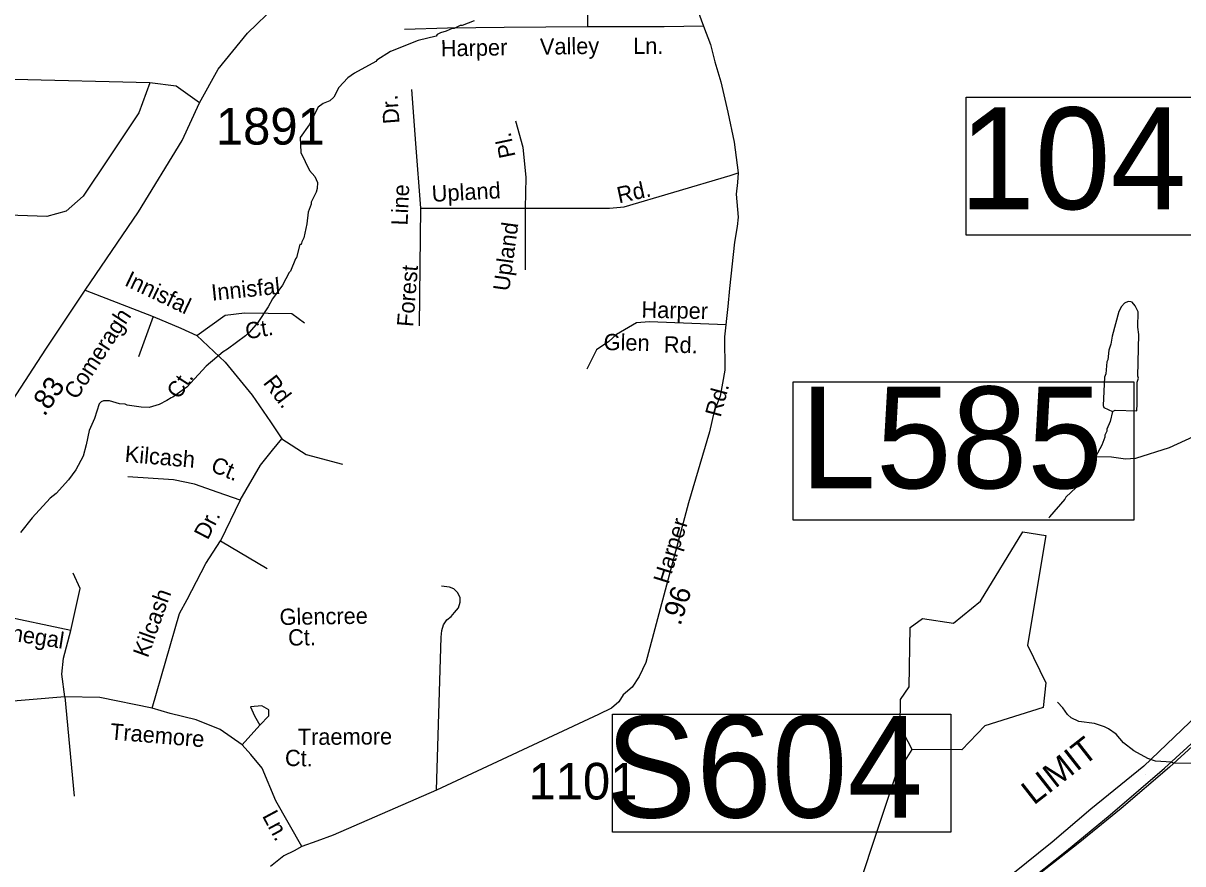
# Model space of a CAD drawing. Extents: x 1551653 to 1702041, y 811336 to 920032.
# Drawn here: x 1584838 to 1589513, y 832897 to 836287 of the extents above; entities that cross this region are included whole.
import ezdxf

# ---------------------------------------------------------------- set-up
doc = ezdxf.new("R2010")
doc.units = 0
for name, color, linetype in [('Old_Level_10', 7, 'Continuous'), ('Old_Level_11', 7, 'Continuous'), ('Old_Level_17', 7, 'Continuous'), ('Old_Level_19', 7, 'Continuous'), ('Old_Level_27', 7, 'Continuous'), ('Old_Level_3', 7, 'Continuous'), ('Old_Level_31', 7, 'Continuous'), ('Old_Level_32', 7, 'Continuous'), ('Old_Level_35', 7, 'Continuous'), ('Old_Level_59', 7, 'Continuous'), ('Old_Level_60', 7, 'Continuous'), ('Old_Level_62', 7, 'Continuous'), ('Old_Level_8', 7, 'Continuous')]:
    doc.layers.add(name, color=color, linetype=linetype)

msp = doc.modelspace()

# ---------------------------------------------------------------- linework, layer by layer
at = {"layer": 'Old_Level_27'}
for points in [[(1585234.947, 830561.484), (1585517.339, 830735.004), (1585731.831, 830866.826), (1586987.103, 831603.033), (1587589.659, 831954.633), (1587938.231, 832161.107), (1588134.784, 832284.159), (1588329.681, 832416.103), (1588524.132, 832555.629), (1588689.213, 832669.856), (1588867.775, 832809.715), (1589044.529, 832949.711), (1589220.001, 833094.479), (1589439.862, 833283.072), (1589622.448, 833449.201), (1589847.716, 833655.674), (1590031.346, 833822.704)], [(1589848.535, 833751.256), (1589658.595, 833580.462), (1589540.265, 833466.424), (1589356.341, 833290.294), (1589142.929, 833117.047), (1588986.427, 832984.144), (1588827.554, 832855.988), (1588637.855, 832715.965), (1588488.13, 832602.006), (1588294.582, 832463.126), (1588074.597, 832322.953), (1587900.805, 832204.617), (1587556.975, 832002.89), (1586266.762, 831248.172), (1585718.938, 830927.99), (1585491.044, 830800.795), (1585324.103, 830701.782)]]:
    msp.add_lwpolyline(points, dxfattribs=at)
at = {"layer": 'Old_Level_3'}
msp.add_lwpolyline([(1589942.504, 833729.014), (1589853.101, 833648.633), (1589643.948, 833455.064), (1589459.401, 833286.101), (1589265.012, 833120.419), (1589091.128, 832979.343), (1588910.682, 832837.447), (1588732.697, 832698.012), (1588562.913, 832578.262), (1588369.344, 832439.646), (1588158.551, 832306.773), (1587952.678, 832177.18), (1587662.325, 832005.756), (1587272.726, 831767.075), (1585533.064, 830743.455)], dxfattribs=at)
at = {"layer": 'Old_Level_31'}
msp.add_line((1589362.127, 833257.432), (1589362.127, 833257.432), dxfattribs=at)
for points in [[(1588639.098, 835987.967), (1589616.623, 835987.967), (1589616.623, 835431.4), (1588639.098, 835431.4), (1588639.098, 835987.967)], [(1587942.488, 834841.019), (1589315.965, 834841.019), (1589315.965, 834282.562), (1587942.488, 834282.562), (1587942.488, 834841.019)], [(1587213.886, 833499.738), (1588577.986, 833499.738), (1588577.986, 833024.31), (1587213.886, 833024.31), (1587213.886, 833499.738)]]:
    msp.add_lwpolyline(points, dxfattribs=at)
at = {"layer": 'Old_Level_32'}
for points in [[(1584743.185, 834688.866), (1584928.668, 834972.489), (1585088.102, 835210.396), (1585302.519, 835525.68), (1585479.347, 835812.909), (1585548.554, 835965.343), (1585623.924, 836101.704), (1585742.776, 836246.77), (1585855.829, 836357.019), (1585976.808, 836466.891), (1586075.368, 836530.72), (1586150.736, 836559.733), (1586208.732, 836579.846)], [(1587556.5, 836340.045), (1587580.081, 836274.826), (1587609.498, 836200.741), (1587626.5, 836130.541), (1587650.183, 836050.307), (1587679.408, 835927.474), (1587703.808, 835807.074), (1587721.011, 835683.574), (1587718.219, 835644.44), (1587712.042, 835597.612), (1587720.048, 835505.004), (1587716.543, 835466.415), (1587706.028, 835403.269), (1587684.997, 835217.339), (1587678.966, 835144.801), (1587665.807, 835021.604), (1587666.066, 834888.027), (1587648.468, 834782.329), (1587623.941, 834722.062), (1587604.84, 834638.46), (1587520.256, 834352.702), (1587348.427, 833708.432), (1587321.426, 833652.733), (1587292.925, 833609.134), (1587257.373, 833578.629), (1587239.926, 833549.934), (1587209.625, 833524.334), (1587157.226, 833499.134), (1586504.528, 833194.433), (1586087.983, 833012.403), (1586021.269, 832988.148), (1585961.683, 832967.1), (1585930.137, 832949.559), (1585888.075, 832928.511), (1585835.498, 832886.413)]]:
    msp.add_lwpolyline(points, dxfattribs=at)
at = {"layer": 'Old_Level_35'}
for p, q in [((1586439.571, 835540.987), (1586861.287, 835540.987)), ((1586861.287, 835540.987), (1586861.287, 835292.208)), ((1585088.102, 835210.396), (1585362.505, 835104.193)), ((1585362.505, 835104.193), (1585302.535, 834940.95)), ((1585712.847, 834363.304), (1585633.858, 834198.66)), ((1585633.858, 834198.66), (1585820.96, 834088.231)), ((1585029.37, 833837.098), (1584736.722, 833899.514)), ((1585005.383, 833570.627), (1584698.342, 833544.22)), ((1585005.383, 833570.627), (1585043.763, 833169.721)), ((1585720.212, 833376.176), (1585792.175, 833455.396))]:
    msp.add_line(p, q, dxfattribs=at)
for points in [[(1587106.272, 836993.355), (1587109.848, 836621.359), (1587112.641, 836271.95)], [(1587112.641, 836271.95), (1586777.503, 836269.155), (1586548.491, 836266.359), (1586375.337, 836260.769)], [(1587580.081, 836274.826), (1587422.644, 836271.95), (1587112.641, 836271.95)], [(1585347.885, 836045.556), (1584801.233, 836058.901), (1584414.578, 836085.59), (1584285.692, 836090.038), (1584183.473, 836076.694), (1584103.475, 836063.349)], [(1585347.885, 836045.556), (1585304.324, 835924.853), (1585183.692, 835743.747), (1585080.294, 835588.513), (1585011.361, 835528.145), (1584933.812, 835506.584), (1584580.535, 835519.52)], [(1585548.554, 835965.343), (1585454.549, 836032.211), (1585347.885, 836045.556)], [(1586403.265, 836018.978), (1586420.022, 835800.947), (1586439.571, 835540.987)], [(1586822.188, 835893.191), (1586852.909, 835786.971), (1586864.08, 835663.979), (1586861.287, 835540.987)], [(1586861.287, 835540.987), (1587202.011, 835540.987), (1587260.66, 835546.577), (1587461.744, 835605.278), (1587687.962, 835672.365), (1587721.011, 835683.574)], [(1586439.571, 835540.987), (1586437.262, 835306.967), (1586434.469, 835066.573)], [(1585362.505, 835104.193), (1585472.847, 835056.181), (1585537.614, 835027.373)], [(1585537.614, 835027.373), (1585652.754, 835108.995), (1585729.514, 835118.597), (1585921.415, 835116.197), (1585971.789, 835077.787)], [(1587670.976, 835069.999), (1587362.428, 835082.344), (1587310.77, 835078.495), (1587229.332, 835031.409), (1587198.424, 835002.549), (1587149.348, 834969.978), (1587110.158, 834891.084)], [(1585537.614, 835027.373), (1585652.754, 834919.344), (1585760.699, 834787.31), (1585835.06, 834679.281), (1585880.76, 834610.57)], [(1585712.847, 834363.304), (1585794.404, 834504.942), (1585842.38, 834564.957), (1585880.76, 834610.57)], [(1585880.76, 834610.57), (1585978.986, 834547.246), (1586125.31, 834508.836)], [(1585712.847, 834363.304), (1585624.093, 834394.512), (1585528.143, 834428.121), (1585444.186, 834444.925), (1585259.482, 834456.928)], [(1585358, 833525.015), (1585468.343, 833905.783), (1585499.527, 833963.398), (1585573.888, 834107.436), (1585633.858, 834198.66)], [(1585029.37, 833837.098), (1585067.751, 834006.609), (1585038.965, 834069.026)], [(1586504.528, 833194.433), (1586523.428, 833810.433), (1586525.827, 833838.333), (1586532.228, 833860.232), (1586546.427, 833880.134), (1586562.726, 833893.831), (1586576.827, 833909.734), (1586593.228, 833929.432), (1586599.527, 833951.331), (1586599.826, 833969.333), (1586590.128, 833989.533), (1586574.426, 834005.632), (1586556.329, 834012.033), (1586524.426, 834016.433)], [(1585005.383, 833570.627), (1584993.389, 833661.851), (1585000.585, 833726.668), (1585029.37, 833837.098)], [(1585358, 833525.015), (1585146.91, 833568.227), (1585005.383, 833570.627)], [(1585720.212, 833376.176), (1585631.458, 833438.592), (1585535.508, 833477.002), (1585429.963, 833503.409), (1585358, 833525.015)], [(1585792.175, 833455.396), (1585828.157, 833493.807), (1585828.157, 833517.813), (1585799.372, 833534.617), (1585753.795, 833529.816), (1585770.586, 833493.807), (1585792.175, 833455.396)], [(1585961.683, 832967.1), (1585856.942, 833150.516), (1585801.771, 833282.551), (1585756.194, 833337.765), (1585720.212, 833376.176)]]:
    msp.add_lwpolyline(points, dxfattribs=at)
at = {"layer": 'Old_Level_59'}
msp.add_lwpolyline([(1588367.579, 831852.319), (1588352.61, 831944.541), (1588165.603, 832279.853), (1588117.518, 832412.163), (1588136.588, 832595.582), (1588354.558, 833250.979), (1588422.533, 833357.966)], dxfattribs=at)
at = {"layer": 'Old_Level_60'}
msp.add_lwpolyline([(1588422.533, 833357.966), (1588373.526, 833450.802), (1588375.576, 833559.122), (1588409.615, 833610.948), (1588413.613, 833850.501), (1588463.544, 833885.667), (1588588.523, 833866.7), (1588697.61, 833956.41), (1588868.521, 834235.229), (1588960.59, 834220.21), (1588887.591, 833778.578), (1588960.59, 833626.071), (1588950.542, 833527.799), (1588715.553, 833453.776), (1588622.561, 833357.196), (1588422.533, 833357.966)], dxfattribs=at)
at = {"layer": 'Old_Level_62'}
for points in [[(1586655.599, 836296.362), (1586607.31, 836276.984), (1586599.313, 836277.087), (1586575.219, 836265.399), (1586567.222, 836265.502), (1586543.026, 836253.814), (1586520.983, 836248.072), (1586506.937, 836240.28), (1586502.836, 836234.334), (1586430.35, 836216.904), (1586318.186, 836172.664), (1586263.745, 836137.344), (1586259.644, 836131.397), (1586173.112, 836084.543), (1586146.968, 836066.857), (1586110.468, 836027.334), (1586089.963, 835987.604), (1586073.867, 835973.815), (1586047.722, 835962.178), (1586027.525, 835948.388), (1585990.718, 835876.928), (1585954.116, 835825.408), (1585957.397, 835765.379), (1585992.563, 835692.944), (1586014.196, 835668.697), (1586023.936, 835644.604), (1586023.629, 835620.613), (1586019.528, 835604.67), (1585999.023, 835564.941), (1585998.92, 835556.944), (1585986.514, 835525.109), (1585982.003, 835477.179), (1585969.29, 835421.405), (1585961.088, 835405.513), (1585959.037, 835393.518), (1585952.988, 835393.62), (1585940.378, 835341.793), (1585935.559, 835336.411), (1585915.771, 835286.121), (1585910.543, 835281.457), (1585883.066, 835230.552), (1585842.465, 835175.085), (1585826.061, 835143.302), (1585783.308, 835079.89), (1585750.807, 835040.315), (1585734.71, 835026.525), (1585662.019, 834971.469), (1585643.975, 834961.678), (1585575.59, 834904.212), (1585498.285, 834819.577), (1585441.794, 834778.31), (1585433.796, 834776.413), (1585417.597, 834764.623), (1585385.507, 834749.039), (1585345.317, 834737.556), (1585313.328, 834737.914), (1585257.452, 834746.629), (1585249.557, 834750.73), (1585225.566, 834751.038), (1585185.683, 834763.546), (1585161.692, 834763.853), (1585151.645, 834759.957), (1585143.545, 834752.063), (1585124.886, 834692.342), (1585104.278, 834644.616), (1585092.282, 834586.125), (1585079.056, 834540.962), (1585050.452, 834485.342), (1585019.899, 834445.767), (1584971.302, 834390.403), (1584947.105, 834370.718), (1584874.107, 834291.67), (1584827.457, 834232.256)], [(1589230.336, 834720.69), (1589240.383, 834726.586), (1589328.248, 834723.253), (1589328.658, 834751.448), (1589329.684, 834839.415), (1589333.887, 834855.358), (1589331.939, 834863.355), (1589335.938, 835031.241), (1589332.349, 835061.281), (1589333.067, 835123.207), (1589321.379, 835147.353), (1589309.486, 835161.501), (1589303.539, 835163.552), (1589293.492, 835163.705), (1589277.498, 835157.913), (1589265.297, 835144.072), (1589255.045, 835124.182), (1589227.875, 835024.577), (1589223.569, 834992.641), (1589215.264, 834968.752), (1589210.753, 834928.87), (1589206.652, 834920.923), (1589202.141, 834872.993), (1589197.938, 834859.049), (1589192.606, 834745.143), (1589194.452, 834737.146), (1589230.336, 834720.69)], [(1589230.336, 834720.69), (1589219.776, 834680.859), (1589207.473, 834649.024), (1589207.37, 834641.027), (1589199.168, 834625.136), (1589199.065, 834617.139), (1589186.66, 834585.305), (1589161.541, 834537.63)], [(1589735.174, 834638.362), (1589715.181, 834634.62), (1589707.184, 834638.721), (1589683.193, 834639.028), (1589667.302, 834643.232), (1589603.223, 834636.055), (1589555.036, 834618.677), (1589458.456, 834573.873), (1589321.994, 834531.632), (1589282.009, 834528.146), (1589226.132, 834536.81), (1589161.541, 834537.63)], [(1589161.541, 834537.63), (1589147.802, 834509.846), (1589094.899, 834430.541), (1589082.698, 834414.701), (1589042.201, 834375.229), (1589038.099, 834367.283), (1588975.354, 834296.079), (1588973.2, 834290.132)], [(1589648.95, 833281.891), (1589611.22, 833292.554), (1589595.226, 833292.759), (1589563.34, 833301.166), (1589475.373, 833302.242), (1589467.479, 833306.343), (1589403.502, 833311.162), (1589371.617, 833321.569), (1589316.048, 833352.224), (1589274.422, 833384.776), (1589244.792, 833419.122), (1589213.111, 833441.473), (1589197.22, 833449.675), (1589157.337, 833462.183), (1589093.464, 833471), (1589063.628, 833485.354), (1589047.839, 833499.554), (1589030.102, 833525.749), (1589007.752, 833548.715)]]:
    msp.add_lwpolyline(points, dxfattribs=at)

# ---------------------------------------------------------------- texts
at = {"layer": 'Old_Level_10'}
for s, rotation, p in [('Harper', 0.959925, (1586522.055, 836152.403)), ('Valley', 0.959925, (1586921.679, 836159.098)), ('Ln.', 0.176717, (1587297.056, 836162.47)), ('Dr.', 94.3868, (1586355.32, 835882.925)), ('Pl.', 101.869728, (1586823.434, 835749.921)), ('Line', 87.505608, (1586387.405, 835470.032)), ('Upland', 3.051022, (1586486.653, 835565.935)), ('Rd.', 12.364353, (1587239.66, 835559.851)), ('Upland', 82.247269, (1586797.043, 835203.647)), ('Innisfal', 334.481519, (1585242.479, 835230.757)), ('Forest', 85.323931, (1586409.779, 835060.462)), ('Innisfal', 5.904169, (1585599.572, 835167.235)), ('Harper', 358.601558, (1587330.005, 835099.718)), ('Comeragh', 56.994503, (1585053.074, 834765.013)), ('Ct.', 9.906553, (1585739.397, 835011.245)), ('Glen', 358.601558, (1587177.457, 834968.853)), ('Rd.', 358.601558, (1587420.107, 834958.756)), ('Ct.', 56.994503, (1585466.56, 834766.614)), ('Rd.', 307.549414, (1585802.764, 834836.014)), ('Kilcash', 355.054689, (1585245.651, 834518.081)), ('Ct.', 337.478067, (1585589.518, 834481.467)), ('Dr.', 62.687108, (1585581.718, 834199.947)), ('Kilcash', 70.199564, (1585340.365, 833724.565)), ('Glencree', 0.843256, (1585871.774, 833859.773)), ('Donegal', 351.129586, (1584673.937, 833814.432)), ('Ct.', 0.712092, (1585906.269, 833776.787)), ('Traemore', 355.178783, (1585186.599, 833398.782)), ('Traemore', 0.394367, (1585945.193, 833375.924)), ('Ct.', 358.749022, (1585892.651, 833291.758)), ('Ln.', 298.254878, (1585799.863, 833090.311))]:
    msp.add_text(s, height=65.6167, rotation=rotation, dxfattribs=at).set_placement(p)
at = {"layer": 'Old_Level_11'}
for s, rotation, p in [('Rd.', 74.9007, (1587649.411, 834694.823)), ('Harper', 72.54535, (1587439.326, 834021.915))]:
    msp.add_text(s, height=65.6167, rotation=rotation, dxfattribs=at).set_placement(p)
at = {"layer": 'Old_Level_17'}
for s, rotation, p in [('.83', 56.055094, (1584923.865, 834697.886)), ('.96', 72.413297, (1587487.767, 833854.06))]:
    msp.add_text(s, height=82.0208, rotation=rotation, dxfattribs=at).set_placement(p)
at = {"layer": 'Old_Level_19'}
msp.add_text('LIMIT', height=98.425, rotation=38.126106, dxfattribs=at).set_placement((1588912.288, 833131.267))
at = {"layer": 'Old_Level_31'}
for s, p in [('104', (1588611.86, 835536.572)), ('L585', (1587970.976, 834411.06)), ('S604', (1587185.429, 833083.531))]:
    msp.add_text(s, height=410.1042, dxfattribs=at).set_placement(p)
at = {"layer": 'Old_Level_8'}
for s, p in [('1891', (1585614.687, 835797.046)), ('1101', (1586875.118, 833156.472))]:
    msp.add_text(s, height=147.6375, dxfattribs=at).set_placement(p)

doc.saveas('drawing.dxf')
